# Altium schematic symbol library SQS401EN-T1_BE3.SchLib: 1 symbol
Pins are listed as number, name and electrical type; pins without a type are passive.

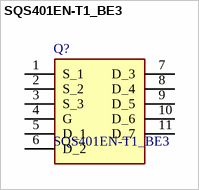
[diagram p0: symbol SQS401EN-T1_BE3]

## SQS401EN-T1_BE3
designator Q?
MOSFET P-CHANNEL 40V (D-S); Manufacturer_Name: Vishay; Geometry.Height: 1.12mm
footprint SQS401ENT1_BE3
pins: 1 S_1, 2 S_2, 3 S_3, 4 G, 5 D_1, 6 D_2, 7 D_3, 8 D_4, 9 D_5, 10 D_6, 11 D_7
